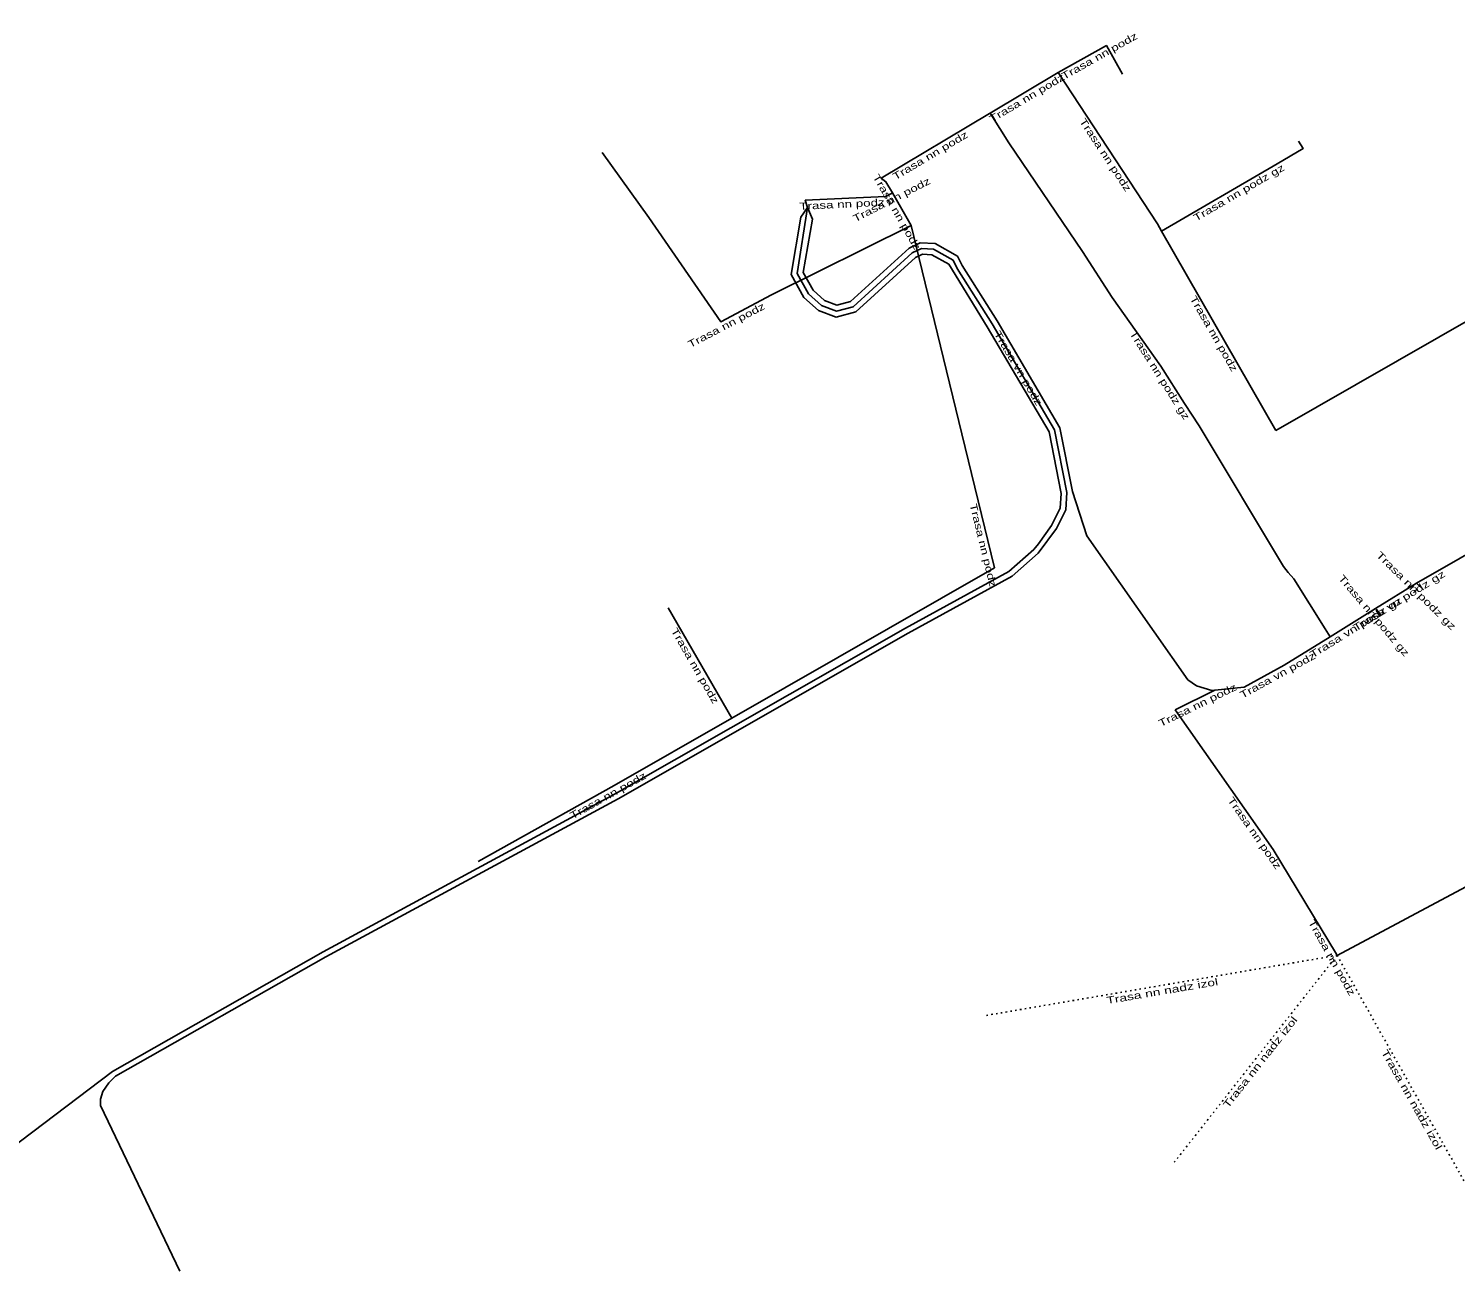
# Model space of a CAD drawing. Extents: x -733620 to -732615, y -1025255 to -1024617.
# Drawn here: x -733417.3 to -733317.4, y -1025016.5 to -1024929.6 of the extents above; entities that cross this region are included whole.
import ezdxf
from ezdxf.enums import TextEntityAlignment as Align

# ---------------------------------------------------------------- set-up
doc = ezdxf.new("R2010")
doc.units = 0
doc.header["$LTSCALE"] = 0.2
doc.linetypes.add('DOTTED', pattern=[1.5, 0.3, -1.2])
doc.linetypes.add('MEDIUM_DASHED', pattern=[4.5, 3, -1.5])
doc.layers.add('11', color=7, linetype='MEDIUM_DASHED', lineweight=25)
doc.layers.add('21', color=7, linetype='Continuous', lineweight=25)
doc.layers.add('20', color=7, linetype='Continuous')

msp = doc.modelspace()

# ---------------------------------------------------------------- linework, layer by layer
at = {"layer": '11', "linetype": 'Continuous'}
for p, q in [((-733355.5, -1024943.44), (-733356.811, -1024941.154)), ((-733320.084, -1024968.504), (-733319.6, -1024968.98)), ((-733372.51, -1024970.22), (-733368.07, -1024977.97)), ((-733334.22, -1024976.009), (-733337, -1024977.37)), ((-733325.7, -1024994.5), (-733325.654, -1024994.581))]:
    msp.add_line(p, q, dxfattribs=at)
at = {"layer": '11', "linetype": 'DOTTED'}
for q in [(-733350.3, -1024998.8), (-733337.06, -1025009.07), (-733314.5, -1025014.4)]:
    msp.add_line((-733325.654, -1024994.581), q, dxfattribs=at)
at = {"layer": '11', "linetype": 'Continuous'}
for points in [[(-733329.94, -1024957.81), (-733312.9, -1024948.04), (-733292.77, -1024936.44), (-733281.31, -1024929.64)], [(-733345.19, -1024932.73), (-733341.82, -1024930.83), (-733340.7, -1024932.84)], [(-733349.989, -1024935.588), (-733349.958, -1024935.569), (-733345.19, -1024932.73)], [(-733345.19, -1024932.73), (-733338.24, -1024943.32), (-733337.95, -1024943.83), (-733329.94, -1024957.81)], [(-733356.811, -1024941.154), (-733357.26, -1024940.37), (-733357.6, -1024940.12), (-733350.009, -1024935.6), (-733349.989, -1024935.588)], [(-733326.147, -1024972.256), (-733326.48, -1024971.71), (-733328.68, -1024968.21), (-733329.08, -1024967.76), (-733329.4, -1024967.34), (-733335.32, -1024957.48), (-733336.35, -1024955.92), (-733338.01, -1024953.29), (-733341.41, -1024948.48), (-733343.5, -1024945.26), (-733348.66, -1024937.65), (-733349.92, -1024935.648), (-733349.95, -1024935.6), (-733349.989, -1024935.588)], [(-733355.5, -1024943.44), (-733365.28, -1024948.31), (-733368.84, -1024950.18), (-733373.88, -1024942.89), (-733377.14, -1024938.33)], [(-733337.95, -1024943.83), (-733329.85, -1024939.11), (-733328.04, -1024938.05), (-733328.35, -1024937.54)], [(-733357.29, -1024941.4), (-733362.912, -1024941.677), (-733362.756, -1024942.171)], [(-733357.29, -1024941.4), (-733356.88, -1024941.189), (-733356.811, -1024941.154)], [(-733368.07, -1024977.97), (-733349.65, -1024967.42), (-733351.94, -1024958.05), (-733354.94, -1024945.76), (-733355.5, -1024943.44)], [(-733322.58, -1024970.74), (-733322.905, -1024970.358), (-733322.966, -1024970.288)], [(-733325.7, -1024994.5), (-733330.14, -1024987.17), (-733337, -1024977.37)], [(-733385.84, -1024988.01), (-733376.31, -1024982.69), (-733368.07, -1024977.97)], [(-733325.654, -1024994.581), (-733315.935, -1024989.398), (-733310.255, -1024986.557), (-733304.214, -1024983.438), (-733303.703, -1024983.642)]]:
    msp.add_lwpolyline(points, dxfattribs=at)
at = {"layer": '21'}
for p, q in [((-733322.966, -1024970.288), (-733320.084, -1024968.504)), ((-733326.147, -1024972.256), (-733322.966, -1024970.288))]:
    msp.add_line(p, q, dxfattribs=at)
for points in [[(-733362.756, -1024942.171), (-733363.224, -1024942.859), (-733363.904, -1024946.869), (-733363.003, -1024948.476), (-733361.989, -1024949.398), (-733360.752, -1024949.856), (-733359.361, -1024949.494), (-733355.193, -1024945.694), (-733354.696, -1024945.456), (-733354.048, -1024945.495), (-733352.861, -1024946.162), (-733350.16, -1024950.544), (-733345.827, -1024957.906), (-733344.982, -1024962.227), (-733345.046, -1024963.237), (-733345.661, -1024964.465), (-733346.584, -1024965.741), (-733346.904, -1024966.137), (-733348.662, -1024967.683), (-733355.902, -1024971.658), (-733376.226, -1024983.26), (-733396.689, -1024994.323), (-733411.437, -1025002.709), (-733420.313, -1025009.427)], [(-733406.724, -1025016.706), (-733412.295, -1025005.093), (-733412.295, -1025004.649), (-733412.13, -1025004.119), (-733411.703, -1025003.513), (-733411.239, -1025003.057), (-733396.495, -1024994.673), (-733376.032, -1024983.61), (-733355.706, -1024972.008), (-733348.43, -1024968.013), (-733346.608, -1024966.409), (-733345.319, -1024964.675), (-733344.668, -1024963.373), (-733344.589, -1024962.15), (-733345.448, -1024957.762), (-733349.819, -1024950.336), (-733352.281, -1024946.443), (-733352.556, -1024945.875), (-733353.932, -1024945.101), (-733354.775, -1024945.051), (-733355.419, -1024945.359), (-733359.557, -1024949.132), (-733360.731, -1024949.437), (-733361.777, -1024949.05), (-733362.686, -1024948.224), (-733363.485, -1024946.798), (-733362.756, -1024942.171)], [(-733362.756, -1024942.171), (-733362.408, -1024942.988), (-733363.066, -1024946.727), (-733362.369, -1024947.972), (-733361.565, -1024948.702), (-733360.71, -1024949.018), (-733359.753, -1024948.77), (-733355.645, -1024945.024), (-733354.854, -1024944.646), (-733353.816, -1024944.707), (-733352.251, -1024945.588), (-733351.931, -1024946.248), (-733349.478, -1024950.128), (-733345.069, -1024957.618), (-733344.196, -1024962.073), (-733343.18, -1024965.192), (-733336.109, -1024975.286), (-733335.499, -1024975.696), (-733334.438, -1024976.032), (-733334.22, -1024976.009)], [(-733320.084, -1024968.504), (-733311.077, -1024963.344), (-733303.01, -1024958.431)], [(-733334.22, -1024976.009), (-733332.165, -1024975.79), (-733329.353, -1024974.241), (-733326.147, -1024972.256)]]:
    msp.add_lwpolyline(points, dxfattribs=at)

# ---------------------------------------------------------------- texts
at = {"layer": '20'}
for s, rotation, width, p in [('Trasa nn podz', 29.414, 1.4, (-733342.1823, -1024931.7799)), ('Trasa nn podz', 30.772, 1.4, (-733347.2574, -1024934.7169)), ('Trasa nn podz', 303.276, 1.4, (-733342.0961, -1024938.6273)), ('Trasa nn podz', 30.774, 1.4, (-733354.0304, -1024938.7518)), ('Trasa nn podz gz', 30.23, 1.4, (-733332.4094, -1024941.3529)), ('Trasa nn podz', 27.19, 1.4, (-733356.7527, -1024941.8545)), ('Trasa nn podz', 299.826, 1.4, (-733356.7185, -1024942.6202)), ('Trasa nn podz', 2.82, 1.4, (-733360.3268, -1024942.2003)), ('Trasa nn podz', 299.811, 1.4, (-733334.5084, -1024951.1422)), ('Trasa nn podz', 27.712, 1.4, (-733368.3248, -1024950.644)), ('Trasa vn podz', 300.483, 1.4, (-733348.2095, -1024953.5637)), ('Trasa nn podz gz', 302.259, 1.4, (-733338.2933, -1024954.0571)), ('Trasa nn podz', 283.734, 1.4, (-733350.6916, -1024965.8951)), ('Trasa nn podz gz', 315.433, 1.45, (-733320.2969, -1024969.2055)), ('Trasa nn podz gz', 310.369, 1.4, (-733323.2673, -1024970.9346)), ('Trasa vn podz gz', 31.752, 1.45, (-733321.1821, -1024969.948)), ('Trasa vn podz gz', 31.757, 1.45, (-733324.2131, -1024971.8237)), ('Trasa nn podz', 299.809, 1.4, (-733370.8536, -1024974.4172)), ('Trasa vn podz', 28.848, 1.4, (-733329.6971, -1024975.173)), ('Trasa nn podz', 26.085, 1.4, (-733335.3234, -1024977.2727)), ('Trasa nn podz', 29.172, 1.4, (-733376.6114, -1024983.6028)), ('Trasa nn podz', 304.992, 1.4, (-733331.6444, -1024986.1531)), ('Trasa nn podz', 299.324, 1.4, (-733326.2433, -1024994.8581)), ('Trasa nn nadz izol', 9.714, 1.45, (-733337.8677, -1024997.3314)), ('Trasa nn nadz izol', 51.791, 1.45, (-733330.8453, -1025002.2271)), ('Trasa nn nadz izol', 299.372, 1.45, (-733320.6431, -1025004.8089))]:
    msp.add_text(s, height=0.5, rotation=rotation, dxfattribs=dict(at, width=width)).set_placement(p, align=Align.CENTER)

doc.saveas('drawing.dxf')
